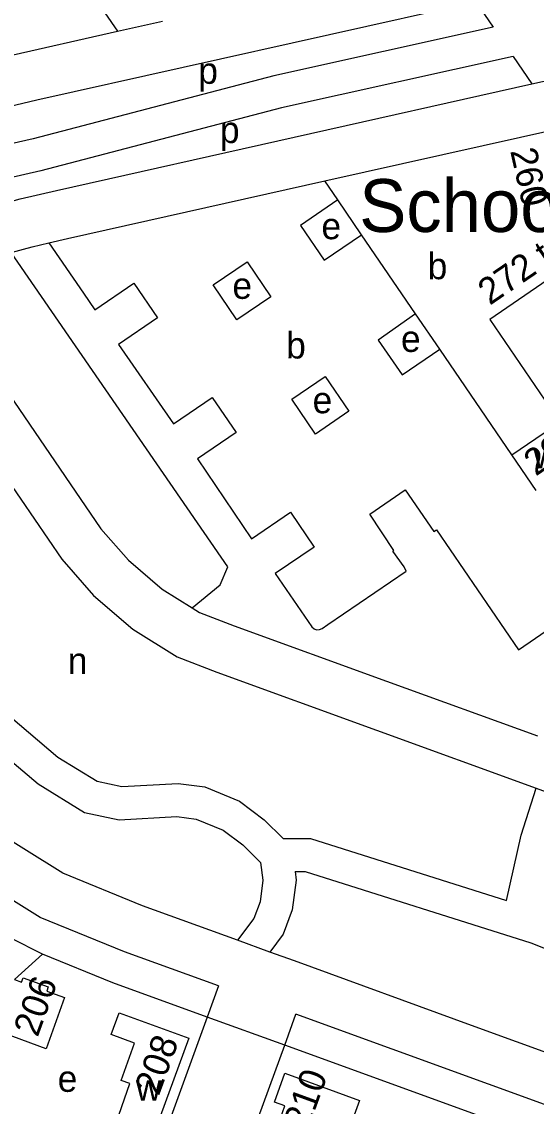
# Model space of a CAD drawing. Extents: x 154320 to 156262, y 382651 to 384180.
# Drawn here: x 155775.5 to 155853.4, y 383033.1 to 383197.4 of the extents above; entities that cross this region are included whole.
import ezdxf

# ---------------------------------------------------------------- set-up
doc = ezdxf.new("R2010")
doc.units = 0
for name, color, linetype in [('BLT_Basislijn', 7, 'Continuous'), ('BLT_Bebouwing', 7, 'Continuous'), ('BLT_Bebouwing_beschrifting', 7, 'Continuous'), ('BLT_Centroide', 7, 'Continuous'), ('BLT_Huisnummer', 7, 'Continuous'), ('BLT_Huisnummer_reeks', 7, 'Continuous'), ('BLT_Onderverdeling_panden', 7, 'Continuous'), ('BLT_Vlakafsluiter', 7, 'Continuous')]:
    doc.layers.add(name, color=color, linetype=linetype)

msp = doc.modelspace()

# ---------------------------------------------------------------- linework, layer by layer
at = {"layer": 'BLT_Basislijn'}
for p, q in [((155844.27, 383200.42), (155846.89, 383196.56)), ((155773.14, 383192.15), (155790.01, 383195.94)), ((155849.92, 383192.11), (155852.75, 383187.97)), ((155852.75, 383187.97), (155858, 383189.14)), ((155853.42, 383081.31), (155858.12, 383079.6)), ((155813.1, 383056.49), (155808.19, 383058.28)), ((155774.44, 383052.32), (155778.65, 383056.19)), ((155816.8, 383055.15), (155813.1, 383056.49)), ((155805.3, 383051.35), (155803.59, 383046.65)), ((155803.59, 383046.65), (155793.51, 383018.93)), ((155815.34, 383042.38), (155817.04, 383047.08)), ((155805.26, 383014.66), (155815.34, 383042.38))]:
    msp.add_line(p, q, dxfattribs=at)
for points in [[(155781.82, 383203.66), (155785.72, 383202.21), (155790.01, 383195.94)], [(155759.27, 383180.32), (155763.06, 383181.61), (155766.88, 383182.79), (155770.73, 383183.86), (155774.62, 383184.83), (155777.81, 383185.54), (155844.27, 383200.42)], [(155846.89, 383196.56), (155813.68, 383189.19), (155777.25, 383179.66), (155765.68, 383177.02), (155754.53, 383173.95)], [(155849.92, 383192.11), (155814.86, 383184.33), (155778.44, 383174.8), (155766.9, 383172.17), (155756.12, 383169.2)], [(155763.8, 383167.07), (155767.59, 383168.36), (155771.42, 383169.53), (155775.28, 383170.58), (155780.77, 383171.85), (155852.75, 383187.97)], [(155773.94, 383162.44), (155777.11, 383163.3), (155779.64, 383163.89)], [(155801.33, 383108.62), (155805.57, 383112.09), (155806.74, 383114.83), (155773.94, 383162.44)], [(155754.67, 383155.35), (155781.59, 383115.97), (155786.38, 383110.5), (155792.35, 383105.37), (155799.06, 383101.19), (155805.08, 383098.89), (155853.42, 383081.31)], [(155765.85, 383152.28), (155787.53, 383120.57), (155791.67, 383115.84), (155796.8, 383111.44), (155801.33, 383108.62)], [(155741.32, 383147.65), (155743.08, 383144.14), (155741.93, 383135.48), (155742.34, 383131.59), (155744.48, 383126.93), (155746.56, 383123.69), (155748.88, 383120.95), (155759.56, 383111.48), (155762.98, 383107.25), (155769.13, 383096.43), (155772.05, 383093.56), (155780.98, 383086.01), (155786.93, 383082.35), (155790.66, 383081.54), (155799.19, 383082.02), (155803.24, 383081.5), (155808.51, 383079.32), (155812.25, 383076.51), (155815.09, 383073.7)], [(155737.15, 383144.82), (155737.92, 383143.28), (155736.89, 383135.55), (155737.46, 383130.24), (155740.09, 383124.52), (155742.53, 383120.71), (155745.3, 383117.45), (155755.93, 383108.02), (155758.83, 383104.43), (155765.13, 383093.35), (155768.68, 383089.86), (155778.04, 383081.95), (155785.04, 383077.64), (155790.27, 383076.51), (155799.01, 383077), (155801.94, 383076.62), (155806.02, 383074.94), (155808.98, 383072.72), (155811.69, 383070.03), (155812.04, 383067.38), (155811.6, 383064.12), (155810.66, 383061.59), (155808.19, 383058.28)], [(155808.19, 383058.28), (155793.79, 383063.51), (155781.76, 383068.42), (155770.32, 383075.56), (155761.52, 383082.89), (155755.26, 383089.5), (155750.96, 383095.03), (155724.08, 383134.36)], [(155805.3, 383051.35), (155791.1, 383056.52), (155778.33, 383061.72), (155765.92, 383069.47), (155756.38, 383077.4), (155749.56, 383084.61), (155744.9, 383090.61), (155723.07, 383122.55)], [(155801.33, 383108.62), (155802.42, 383107.94), (155807.7, 383105.91), (155830.73, 383097.54)], [(155830.73, 383097.54), (155853.63, 383089.22)], [(155815.09, 383073.7), (155819.23, 383073.7), (155848.89, 383064.31), (155851.11, 383074.18), (155853.42, 383081.31)], [(155816.91, 383068.7), (155817.08, 383067.37), (155816.48, 383062.9), (155815.1, 383059.18), (155813.1, 383056.49)], [(155816.91, 383068.7), (155818.46, 383068.7), (155852.58, 383057.9)], [(155778.65, 383056.19), (155773.87, 383058.61)], [(155852.58, 383057.9), (155864.43, 383053.19), (155869.73, 383050.56), (155874.01, 383046.82), (155878.28, 383042.3), (155882.92, 383039.67), (155888.57, 383037.98), (155895.89, 383037.17), (155904.05, 383036.95), (155908.47, 383035.79), (155926.08, 383026.11), (155919.49, 383022.53), (155917.44, 383018.56)], [(155803.59, 383046.65), (155789.3, 383051.85), (155778.65, 383056.19)], [(155843.64, 383045.39), (155816.8, 383055.15)], [(155903.98, 383015.47), (155817.04, 383047.08)], [(155917.44, 383018.56), (155843.64, 383045.39)], [(155902.27, 383010.77), (155815.34, 383042.38)]]:
    msp.add_lwpolyline(points, dxfattribs=at)
at = {"layer": 'BLT_Bebouwing'}
msp.add_line((155821.39, 383173.27), (155858.01, 383181.48), dxfattribs=at)
for points in [[(155779.64, 383163.89), (155782.44, 383164.54), (155821.39, 383173.27)], [(155823.36, 383170.4), (155817.71, 383166.53), (155821.3, 383161.27), (155826.95, 383165.14)], [(155779.64, 383163.89), (155784.88, 383156.29), (155786.59, 383153.77), (155792.52, 383157.78), (155796.1, 383152.53), (155790.18, 383148.49), (155798.53, 383136.48), (155804.37, 383140.47), (155807.98, 383135.19), (155802.16, 383131.21), (155810.32, 383119.06), (155816.22, 383123.12), (155819.79, 383117.83), (155813.91, 383113.82), (155818.33, 383107.37)], [(155870.34, 383145.59), (155859.58, 383161.33), (155846.37, 383152.3), (155856.99, 383136.76)], [(155835.14, 383153.15), (155829.51, 383149.18), (155833.14, 383143.93), (155838.8, 383147.81)], [(155821.88, 383106.08), (155833.73, 383114.19), (155833.41, 383114.85), (155831.7, 383117.2), (155831.88, 383117.32), (155828.21, 383122.83), (155833.57, 383126.5), (155837.93, 383120.18), (155838.3, 383120.44), (155850.73, 383102.28), (155856.7, 383106.35)], [(155818.33, 383107.37), (155819.44, 383105.75), (155819.78, 383105.46), (155820.17, 383105.31), (155820.61, 383105.32), (155821.01, 383105.48), (155821.88, 383106.08)], [(155774.44, 383052.32), (155775.51, 383051.94), (155775.73, 383052.56), (155779.55, 383051.2), (155779.33, 383050.58), (155782.02, 383049.63), (155779.23, 383041.84), (155772.84, 383044.18), (155768.05, 383039.66), (155770.99, 383038.54), (155769.07, 383033.27), (155763.16, 383035.43), (155761.49, 383030.57)]]:
    msp.add_lwpolyline(points, dxfattribs=at)
for points in [[(155809.66, 383161.02), (155813.26, 383155.75), (155808.11, 383152.26), (155804.51, 383157.52)], [(155816.4, 383140.21), (155821.48, 383143.66), (155825.07, 383138.43), (155820, 383134.95)], [(155790.29, 383047.26), (155800.81, 383043.44), (155794.99, 383027.46), (155789.43, 383029.47), (155791.92, 383036.56), (155790.58, 383037.04), (155792.62, 383042.69), (155789.09, 383043.98)], [(155815.34, 383038.14), (155826.66, 383034.03), (155823.68, 383025.81), (155821.96, 383021.11), (155817.81, 383022.67), (155817.2, 383020.97), (155818.61, 383020.47), (155817.26, 383016.69), (155808.67, 383019.81), (155813.04, 383031.76), (155814.64, 383031.16), (155815.37, 383033.18), (155813.77, 383033.75)]]:
    msp.add_lwpolyline(points, close=True, dxfattribs=at)
at = {"layer": 'BLT_Onderverdeling_panden'}
for p, q in [((155823.36, 383170.4), (155821.39, 383173.27)), ((155826.95, 383165.14), (155823.36, 383170.4)), ((155835.14, 383153.15), (155826.95, 383165.14)), ((155838.8, 383147.81), (155835.14, 383153.15)), ((155849.74, 383131.79), (155838.8, 383147.81)), ((155849.74, 383131.79), (155856.99, 383136.76)), ((155853.43, 383126.39), (155849.74, 383131.79))]:
    msp.add_line(p, q, dxfattribs=at)
at = {"layer": 'BLT_Vlakafsluiter'}
for p, q in [((155790.01, 383195.94), (155796.82, 383197.47)), ((155815.34, 383042.38), (155803.59, 383046.65))]:
    msp.add_line(p, q, dxfattribs=at)

# ---------------------------------------------------------------- texts
at = {"layer": 'BLT_Bebouwing_beschrifting'}
msp.add_text('School', height=8, dxfattribs=at).set_placement((155826.62, 383165.55))
at = {"layer": 'BLT_Centroide'}
for s, p in [('p', (155802.26, 383187.99)), ('p', (155805.53, 383179.02)), ('e', (155820.9, 383164.45)), ('b', (155836.98, 383158.4)), ('e', (155807.42, 383155.42)), ('b', (155815.56, 383146.39)), ('e', (155832.94, 383147.38)), ('e', (155819.56, 383138.09)), ('w', (155852.97, 383129.75)), ('n', (155782.5, 383098.61)), ('w', (155792.81, 383033.99))]:
    msp.add_text(s, height=4, dxfattribs=at).set_placement(p)
msp.add_text('e', height=4, rotation=359.5, dxfattribs=at).set_placement((155780.96, 383035.33))
at = {"layer": 'BLT_Huisnummer'}
for s, rotation, p in [('292', 34.361, (155853.33, 383128.48)), ('206', 70.0188, (155777.93, 383043.48)), ('208', 69.8792, (155796.27, 383034.58)), ('210', 70.0191, (155818.82, 383029.41))]:
    msp.add_text(s, height=4, rotation=rotation, dxfattribs=at).set_placement(p)
at = {"layer": 'BLT_Huisnummer_reeks'}
for s, rotation, p in [('260', 282.645, (155849.46, 383177.84)), ('272 t/m 290', 34.361, (155846.38, 383154.36))]:
    msp.add_text(s, height=4, rotation=rotation, dxfattribs=at).set_placement(p)

doc.saveas('drawing.dxf')
